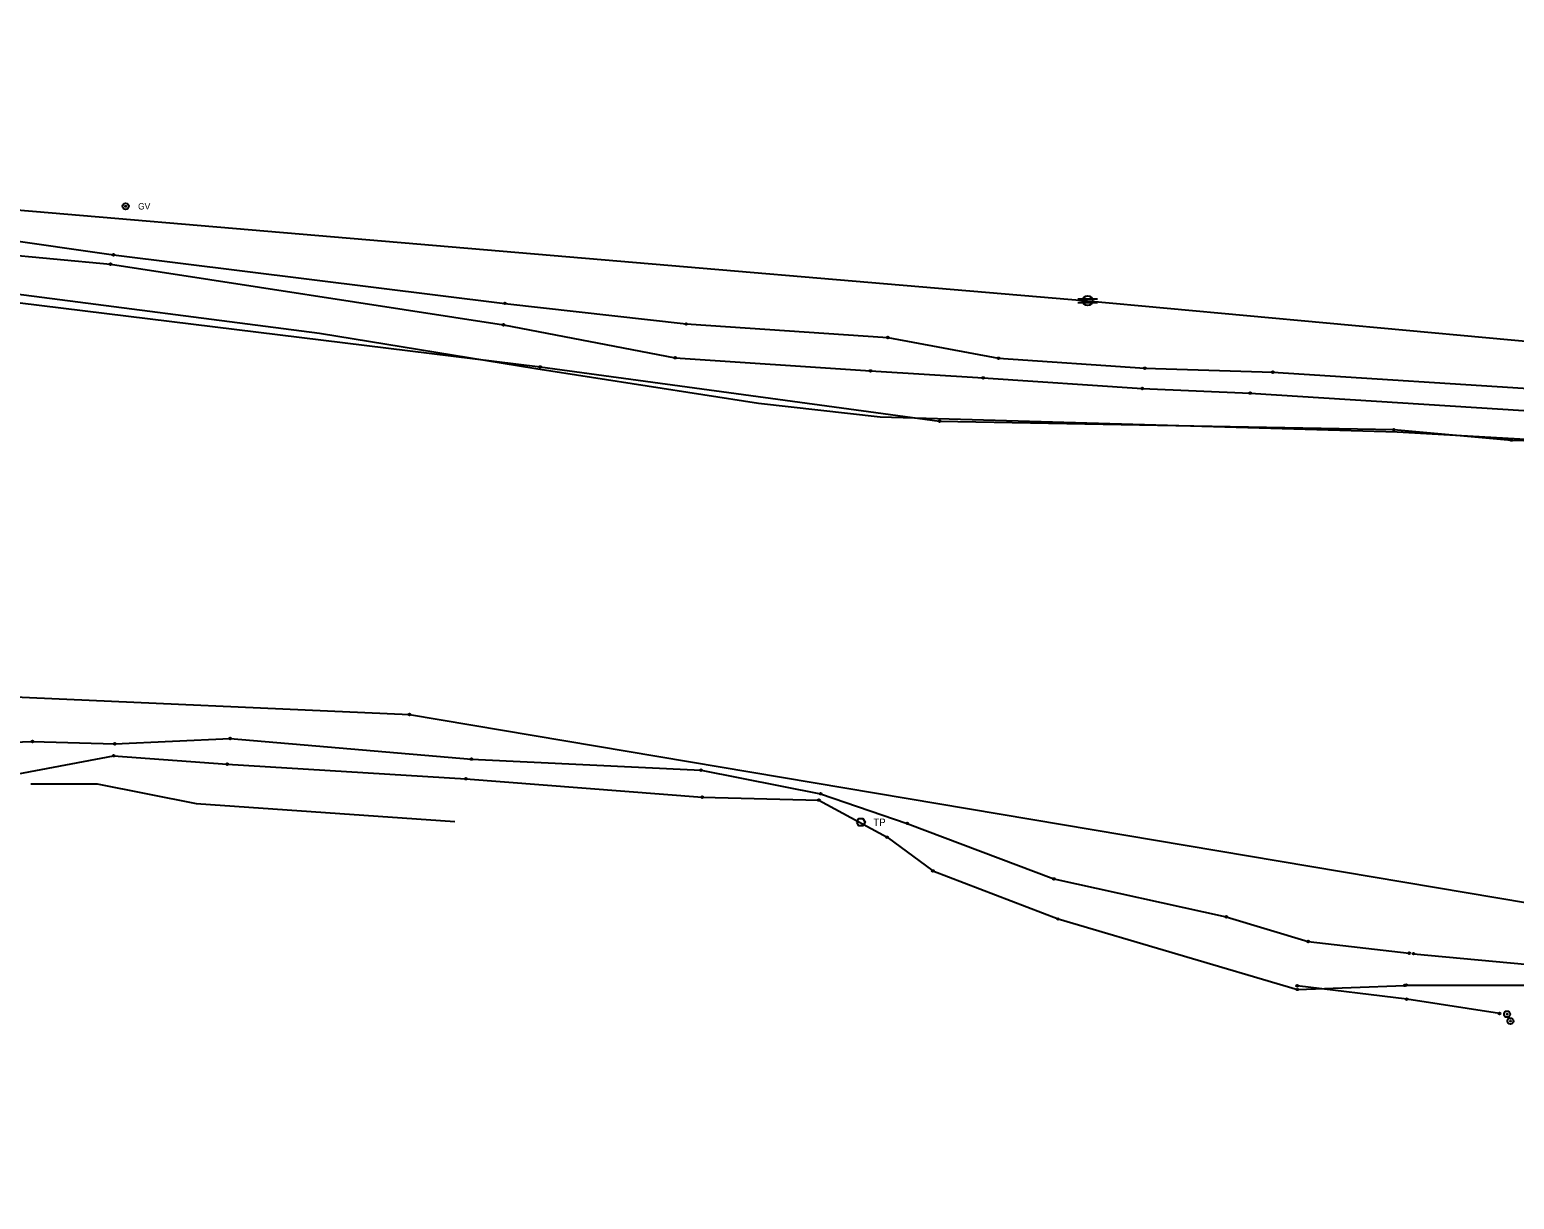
# Model space of a CAD drawing. Extents: x 20500343 to 20505311, y 7953484 to 7954193.
# Drawn here: x 20503940.9 to 20504268.9, y 7953562.2 to 7953820.7 of the extents above; entities that cross this region are included whole.
import ezdxf

# ---------------------------------------------------------------- set-up
doc = ezdxf.new("R2010")
doc.units = 0
for name, color, linetype in [('C-PROP-LINE-LOT', 7, 'Continuous'), ('V-ANNO-BNDY', 7, 'Continuous'), ('V-ANNO-NOTE', 7, 'Continuous'), ('V-CTRL-HVPT', 7, 'Continuous'), ('V-MON-FND', 7, 'Continuous')]:
    doc.layers.add(name, color=color, linetype=linetype)

msp = doc.modelspace()

# ---------------------------------------------------------------- linework, layer by layer
at = {"layer": 'C-PROP-LINE-LOT'}
for points in [[(20503437.68, 7953820.69), (20503685.54, 7953801.97), (20503900.73, 7953784.06), (20504174.6, 7953760.81), (20504420.99, 7953738.08), (20504670.9, 7953722.47), (20504838.2, 7953713.61), (20505006.28, 7953702.11), (20505174.11, 7953700.54)], [(20503790.68, 7953784.4), (20503808.98, 7953784.03), (20503909.45, 7953778.06), (20503959.38, 7953770.95), (20504045.88, 7953760.22), (20504085.92, 7953755.66), (20504130.44, 7953752.67), (20504154.9, 7953748.08), (20504187.24, 7953745.87), (20504215.5, 7953745), (20504277.71, 7953741.02), (20504317.61, 7953739.57), (20504358.43, 7953733.33), (20504412.41, 7953729.48), (20504477.58, 7953724.58), (20504548.69, 7953718.7), (20504593.57, 7953715.94), (20504642.65, 7953712.07), (20504674.79, 7953710.13), (20504682, 7953710.89), (20504686.23, 7953720.21)], [(20503696.87, 7953782.64), (20503809.83, 7953779.43), (20503869.03, 7953768.03), (20503892.5, 7953770.66), (20503908.3, 7953773.6), (20503958.75, 7953768.88), (20504045.54, 7953755.47), (20504083.49, 7953748.2), (20504126.62, 7953745.29), (20504151.53, 7953743.73), (20504186.68, 7953741.39), (20504210.51, 7953740.4), (20504276.78, 7953736.15)], [(20503699.26, 7953775.1), (20503803.54, 7953764.58), (20503866.33, 7953759.03), (20503928.53, 7953761.61), (20504053.64, 7953746.16), (20504141.91, 7953734.18), (20504242.25, 7953732.31), (20504268.23, 7953730.01), (20504338.72, 7953728.07), (20504367.8, 7953726.96), (20504422.51, 7953721.81), (20504479.99, 7953718.52), (20504541.43, 7953712.4), (20504605.71, 7953707.78), (20504671.49, 7953704.84), (20504755.78, 7953700.92), (20504815.67, 7953699.69), (20504872.03, 7953696.31), (20505039.13, 7953696.21), (20505092.16, 7953700.52), (20505136.96, 7953703.53), (20505186.48, 7953709.16)], [(20503774.54, 7953770.56), (20503865.82, 7953759.32), (20503909.8, 7953760.07), (20503935.64, 7953762.61), (20504004.9, 7953753.63), (20504052.71, 7953745.8), (20504101.86, 7953738.14), (20504128.8, 7953735.15), (20504243.01, 7953731.82), (20504285.64, 7953729.43), (20504338.85, 7953727.9), (20504393.63, 7953724.94), (20504522.96, 7953714.6), (20504559.53, 7953710.68), (20504601.53, 7953709.61)], [(20503634.24, 7953675.44), (20503739.17, 7953665.18), (20503779.4, 7953664.67), (20503844.8, 7953670.17), (20503935.89, 7953673.31), (20504024.77, 7953669.37)], [(20504024.77, 7953669.37), (20504354.36, 7953613.84), (20504403.94, 7953611.06), (20504480.92, 7953605.95), (20504541.55, 7953600.29), (20504620.66, 7953595.28), (20504701.53, 7953590.77), (20504892.22, 7953579.68), (20504974.75, 7953574.83)], [(20503633.76, 7953662.54), (20503685.43, 7953656.65), (20503740.96, 7953651.29), (20503787.46, 7953648.45), (20503832.54, 7953645.05), (20503911.03, 7953648.63), (20503919.54, 7953652.71), (20503959.44, 7953660.25), (20503984.54, 7953658.4), (20504037.26, 7953655.17), (20504089.47, 7953651.11), (20504115.23, 7953650.46), (20504130.28, 7953642.23), (20504140.41, 7953634.8), (20504168.06, 7953624.18), (20504220.93, 7953608.62), (20504244.64, 7953609.51)], [(20503633.79, 7953664.64), (20503685.04, 7953659.39), (20503740.52, 7953656.21), (20503787.2, 7953656.16), (20503841.43, 7953655.18), (20503892.94, 7953658.2), (20503916.96, 7953662.59), (20503941.48, 7953663.41), (20503959.68, 7953662.87), (20503985.16, 7953664.06), (20504038.46, 7953659.51), (20504089.19, 7953657.06), (20504115.62, 7953651.86), (20504134.72, 7953645.31), (20504167.14, 7953633.03), (20504205.24, 7953624.66), (20504223.31, 7953619.19), (20504245.65, 7953616.64)], [(20503941.12, 7953654.01), (20503955.78, 7953654.06), (20503977.69, 7953649.69), (20504034.84, 7953645.73)], [(20504246.56, 7953616.51), (20504293.41, 7953612.16), (20504342.32, 7953610.98), (20504402.14, 7953607.9), (20504485.85, 7953600.21), (20504541.12, 7953597.7), (20504568.97, 7953596.35), (20504645.79, 7953589.23), (20504701.93, 7953586.24), (20504764.32, 7953586.16), (20504836, 7953579.91), (20504942.46, 7953569.69), (20504990.68, 7953565.15)], [(20504265.6, 7953603.29), (20504245.08, 7953606.46), (20504220.88, 7953609.43)], [(20504245.01, 7953609.59), (20504293.38, 7953609.52), (20504342.41, 7953608.24), (20504400.78, 7953602.78), (20504485.23, 7953596.26), (20504540.28, 7953594.35), (20504568.66, 7953593.24), (20504644.38, 7953584.7), (20504700.91, 7953581.94), (20504764.05, 7953583.43), (20504836, 7953575.34), (20504894.29, 7953574.48), (20504941.93, 7953567.42), (20504990.58, 7953562.23)]]:
    msp.add_lwpolyline(points, dxfattribs=at)
at = {"layer": 'V-ANNO-BNDY'}
for centre, radius in [((20503962.09, 7953781.66), 0.685), ((20503962.09, 7953781.66), 0.114), ((20504267.27, 7953603.14), 0.685), ((20504267.27, 7953603.14), 0.114), ((20504268.01, 7953601.61), 0.685), ((20504268.01, 7953601.61), 0.114)]:
    msp.add_circle(centre, radius, dxfattribs=at)
at = {"layer": 'V-ANNO-NOTE'}
for centre in [(20503959.38, 7953770.95), (20503958.75, 7953768.88), (20504045.88, 7953760.22), (20504045.54, 7953755.47), (20504085.92, 7953755.66), (20504130.44, 7953752.67), (20504083.49, 7953748.2), (20504154.9, 7953748.08), (20504053.64, 7953746.16), (20504126.62, 7953745.29), (20504151.53, 7953743.73), (20504187.24, 7953745.87), (20504215.5, 7953745), (20504186.68, 7953741.39), (20504210.51, 7953740.4), (20504141.91, 7953734.18), (20504242.25, 7953732.31), (20504268.23, 7953730.01), (20504024.77, 7953669.37), (20504024.77, 7953669.37), (20503941.48, 7953663.41), (20503959.68, 7953662.87), (20503985.16, 7953664.06), (20503959.44, 7953660.25), (20503984.54, 7953658.4), (20504038.46, 7953659.51), (20504037.26, 7953655.17), (20504089.19, 7953657.06), (20504115.62, 7953651.86), (20504089.47, 7953651.11), (20504115.23, 7953650.46), (20504134.72, 7953645.31), (20504130.28, 7953642.23), (20504140.41, 7953634.8), (20504167.14, 7953633.03), (20504168.06, 7953624.18), (20504205.24, 7953624.66), (20504223.31, 7953619.19), (20504245.65, 7953616.64), (20504246.56, 7953616.51), (20504220.88, 7953609.43), (20504244.64, 7953609.51), (20504245.01, 7953609.59), (20504220.93, 7953608.62), (20504245.08, 7953606.46), (20504265.6, 7953603.29)]:
    msp.add_circle(centre, 0.2, dxfattribs=at)
at = {"layer": 'V-CTRL-HVPT'}
for p, q in [((20504172.4, 7953761.25), (20504176.8, 7953761.25)), ((20504172.4, 7953760.37), (20504176.8, 7953760.37))]:
    msp.add_line(p, q, dxfattribs=at)
msp.add_circle((20504174.6, 7953760.81), 1.1, dxfattribs=at)
at = {"layer": 'V-MON-FND'}
msp.add_lwpolyline([(20504123.6, 7953645.56), (20504124.05, 7953646.35), (20504124.97, 7953646.35), (20504125.42, 7953645.56), (20504124.97, 7953644.77), (20504124.05, 7953644.77), (20504123.6, 7953645.56)], dxfattribs=at)

# ---------------------------------------------------------------- texts
at = {"layer": 'V-ANNO-BNDY'}
msp.add_text('GV', height=1.399, dxfattribs=at).set_placement((20503964.83, 7953780.96))
at = {"layer": 'V-MON-FND'}
msp.add_text('TP', height=1.599, dxfattribs=at).set_placement((20504127.25, 7953644.76))

doc.saveas('drawing.dxf')
